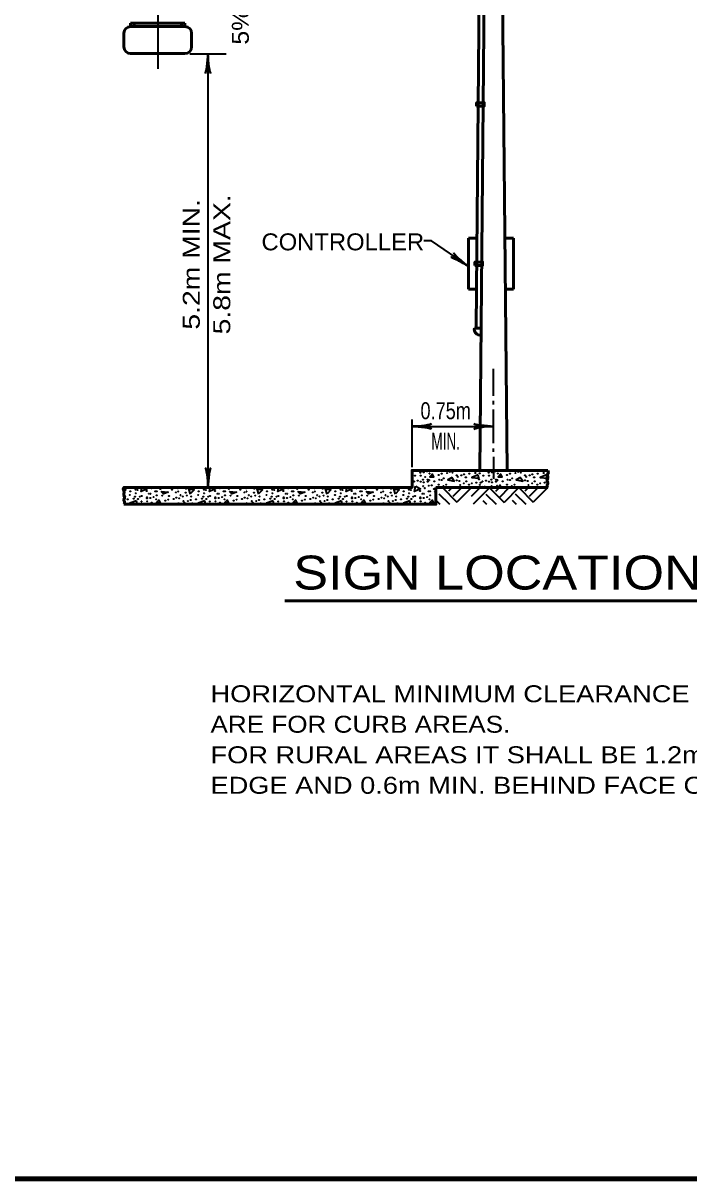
# Model space of a CAD drawing. Extents: x -35 to 821, y -10 to 534.
# Drawn here: x 357.6 to 475.5, y 1.2 to 205.9 of the extents above; entities that cross this region are included whole.
import ezdxf
from ezdxf.enums import TextEntityAlignment as Align

# ---------------------------------------------------------------- set-up
doc = ezdxf.new("R2010")
doc.units = 0
doc.header["$LTSCALE"] = 1.2
doc.layers.add('1', color=7, linetype='Continuous', lineweight=35)

msp = doc.modelspace()

# ---------------------------------------------------------------- linework, layer by layer
at = {"layer": '1', "lineweight": 53}
for p, q in [((439.528, 239.184), (438.487, 126.685)), ((442.245, 239.184), (443.287, 126.685)), ((438.395, 213.985), (437.884, 158.795)), ((376.67, 205.885), (386.27, 205.885)), ((376.67, 205.885), (376.67, 205.285)), ((376.67, 205.285), (386.27, 205.285)), ((377.27, 205.885), (377.27, 205.285)), ((385.67, 205.885), (385.67, 205.285)), ((386.27, 205.885), (386.27, 205.285)), ((375.47, 204.085), (375.47, 201.685)), ((387.47, 204.085), (387.47, 201.685)), ((376.67, 200.485), (386.27, 200.485)), ((436.467, 167.787), (436.467, 158.795)), ((437.967, 167.787), (436.467, 167.787)), ((444.405, 167.787), (442.906, 167.787)), ((444.405, 167.787), (444.405, 158.795)), ((437.884, 158.795), (436.467, 158.795)), ((437.884, 158.795), (437.82, 151.883)), ((444.405, 158.795), (442.989, 158.795)), ((438.72, 151.883), (437.52, 151.883)), ((450.487, 123.685), (430.687, 123.685)), ((403.971, 103.606), (518.449, 103.606))]:
    msp.add_line(p, q, dxfattribs=at)
at = {"layer": '1'}
for p, q in [((381.47, 211.285), (381.47, 197.779)), ((387.17, 200.438), (393.594, 200.438)), ((390.36, 200.438), (390.36, 123.685)), ((440.887, 139.885), (440.887, 144.685)), ((440.887, 138.385), (440.887, 138.985)), ((440.887, 131.485), (440.887, 137.485)), ((426.487, 127.285), (426.487, 135.685)), ((426.487, 134.485), (440.887, 134.485)), ((440.887, 129.985), (440.887, 130.585)), ((440.887, 129.085), (440.887, 125.185)), ((430.432, 122.984), (430.687, 122.955)), ((430.687, 122.729), (430.432, 122.984)), ((431.863, 123.637), (434.431, 121.069)), ((433.567, 123.637), (432.943, 123.013)), ((435.295, 123.637), (433.711, 122.053)), ((436.999, 123.637), (434.431, 121.069)), ((438.535, 123.637), (436.951, 122.053)), ((440.239, 123.637), (437.287, 120.685)), ((439.131, 123.685), (439.168, 123.944)), ((439.216, 123.92), (439.628, 123.685)), ((440.119, 123.637), (442.759, 120.997)), ((441.943, 123.637), (441.271, 122.941)), ((443.671, 123.637), (442.015, 121.981)), ((445.375, 123.637), (442.759, 120.997)), ((445.375, 123.637), (447.943, 121.069)), ((447.079, 123.637), (446.455, 123.013)), ((448.807, 123.637), (447.223, 122.053)), ((450.511, 123.637), (447.943, 121.069)), ((385.192, 120.872), (384.848, 120.685)), ((385.28, 120.685), (385.144, 120.896)), ((397.288, 120.872), (396.944, 120.685)), ((397.376, 120.685), (397.24, 120.896)), ((409.384, 120.872), (409.04, 120.685)), ((409.472, 120.685), (409.336, 120.896)), ((421.48, 120.872), (421.136, 120.685)), ((421.568, 120.685), (421.432, 120.896)), ((430.687, 121.405), (431.407, 120.685)), ((431.239, 122.557), (433.111, 120.685)), ((438.991, 121.333), (439.639, 120.685)), ((439.543, 122.485), (441.362, 120.685)), ((444.199, 121.405), (444.919, 120.685)), ((444.751, 122.557), (446.623, 120.685))]:
    msp.add_line(p, q, dxfattribs=at)
at = {"layer": '1', "lineweight": 158}
msp.add_line((814.384, 1.25), (22.784, 1.25), dxfattribs=at)
at = {"layer": '1', "lineweight": 53}
for points in [[(437.894, 191.186), (437.894, 191.786), (439.244, 191.786), (439.244, 191.186)], [(437.603, 162.988), (437.603, 163.588), (438.953, 163.588), (438.953, 162.988)]]:
    msp.add_lwpolyline(points, close=True, dxfattribs=at)
at = {"layer": '1'}
for points in [[(436.444, 162.857), (429.937, 167.319), (428.552, 167.319)], [(430.096, 126.056), (429.64, 125.576), (430.336, 125.528), (430.096, 126.008)], [(433.576, 125.432), (432.784, 125), (433.96, 124.784), (433.528, 125.456)], [(438.16, 125.888), (437.032, 125.432), (438.28, 125.288), (438.16, 125.84)], [(442.192, 126.056), (441.736, 125.576), (442.432, 125.528), (442.192, 126.008)], [(445.672, 125.432), (444.88, 125), (446.056, 124.784), (445.624, 125.456)], [(450.256, 125.888), (449.128, 125.432), (450.376, 125.288), (450.256, 125.84)], [(375.354, 123.341), (375.808, 123.248), (375.508, 122.927)], [(379.148, 123.685), (379.576, 123.44), (378.544, 122.936), (378.651, 123.685)], [(387.256, 122.48), (386.968, 123.44), (387.904, 123.248), (387.232, 122.528)], [(391.244, 123.685), (391.672, 123.44), (390.64, 122.936), (390.747, 123.685)], [(399.352, 122.48), (399.064, 123.44), (400, 123.248), (399.328, 122.528)], [(403.34, 123.685), (403.768, 123.44), (402.736, 122.936), (402.843, 123.685)], [(411.448, 122.48), (411.16, 123.44), (412.096, 123.248), (411.424, 122.528)], [(415.436, 123.685), (415.864, 123.44), (414.832, 122.936), (414.939, 123.685)], [(423.544, 122.48), (423.256, 123.44), (424.192, 123.248), (423.52, 122.528)], [(427.12, 123.92), (427.96, 123.44), (426.928, 122.936), (427.072, 123.944)], [(377.68, 121.328), (376.552, 120.872), (377.8, 120.728), (377.68, 121.28)], [(381.712, 121.496), (381.256, 121.016), (381.952, 120.968), (381.712, 121.448)], [(389.776, 121.328), (388.648, 120.872), (389.896, 120.728), (389.776, 121.28)], [(393.808, 121.496), (393.352, 121.016), (394.048, 120.968), (393.808, 121.448)], [(401.872, 121.328), (400.744, 120.872), (401.992, 120.728), (401.872, 121.28)], [(405.904, 121.496), (405.448, 121.016), (406.144, 120.968), (405.904, 121.448)], [(413.968, 121.328), (412.84, 120.872), (414.088, 120.728), (413.968, 121.28)], [(418, 121.496), (417.544, 121.016), (418.24, 120.968), (418, 121.448)], [(426.064, 121.328), (424.936, 120.872), (426.184, 120.728), (426.064, 121.28)], [(430.096, 121.496), (429.64, 121.016), (430.336, 120.968), (430.096, 121.448)]]:
    msp.add_lwpolyline(points, dxfattribs=at)
at = {"layer": '1', "lineweight": 53}
for points in [[(375.487, 120.685), (375.596, 120.843), (375.602, 121.098), (375.471, 121.392), (375.491, 121.562), (375.628, 121.89), (375.478, 122.302), (375.445, 122.492), (375.511, 122.897), (375.491, 123.087), (375.354, 123.342), (375.487, 123.685), (426.487, 123.685), (426.487, 126.685), (450.487, 126.685)], [(450.487, 126.685), (450.62, 126.342), (450.482, 126.087), (450.463, 125.897), (450.528, 125.492), (450.495, 125.302), (450.345, 124.89), (450.482, 124.562), (450.502, 124.392), (450.371, 124.098), (450.377, 123.843), (450.487, 123.685)], [(430.687, 123.685), (430.687, 120.685), (375.487, 120.685)]]:
    msp.add_lwpolyline(points, dxfattribs=at)
at = {"layer": '1'}
for points in [[(382.048, 122.984), (383.296, 122.84), (382.48, 122.552)], [(394.144, 122.984), (395.392, 122.84), (394.576, 122.552)], [(406.24, 122.984), (407.488, 122.84), (406.672, 122.552)], [(418.336, 122.984), (419.584, 122.84), (418.768, 122.552)]]:
    msp.add_lwpolyline(points, close=True, dxfattribs=at)
for centre in [(426.679, 126.58), (426.981, 125.743), (427.474, 124.868), (427.935, 126.3), (427.951, 126.501), (427.983, 125.759), (428.396, 125.043), (428.539, 126.363), (428.794, 125.536), (429.128, 126.517), (429.223, 125.059), (429.503, 124.963), (429.566, 126.141), (431.173, 125.886), (431.3, 125.027), (431.713, 126.093), (431.713, 124.979), (432.095, 125.266), (432.684, 126.204), (433.161, 126.437), (433.638, 126.284), (434.306, 126.628), (434.385, 125.807), (434.385, 124.916), (434.576, 125.552), (434.846, 124.804), (435.196, 125.807), (435.673, 125.998), (435.785, 126.628), (435.944, 125.441), (436.007, 125.441), (436.612, 126.125), (437.677, 126.236), (437.932, 126.612), (438.313, 125.122), (438.441, 126.188), (438.775, 126.58), (439.077, 125.743), (439.57, 124.868), (440.031, 126.3), (440.047, 126.501), (440.079, 125.759), (440.492, 125.043), (440.635, 126.363), (440.89, 125.536), (441.224, 126.517), (441.319, 125.059), (441.599, 124.963), (441.662, 126.141), (443.269, 125.886), (443.396, 125.027), (443.809, 126.093), (443.809, 124.979), (444.191, 125.266), (444.78, 126.204), (445.257, 126.437), (445.734, 126.284), (446.402, 126.628), (446.481, 125.807), (446.481, 124.916), (446.672, 125.552), (446.942, 124.804), (447.292, 125.807), (447.769, 125.998), (447.881, 126.628), (448.04, 125.441), (448.103, 125.441), (448.708, 126.125), (449.773, 126.236), (450.028, 126.612), (376.609, 122.975), (377.547, 123.277), (377.897, 123.198), (379.519, 123.023), (380.346, 123.547), (381.022, 122.988), (381.294, 123.007), (381.946, 123.404), (383.981, 123.277), (384.697, 122.784), (385.031, 123.547), (385.079, 122.959), (386.399, 122.752), (386.447, 123.468), (388.705, 122.975), (389.643, 123.277), (389.993, 123.198), (391.615, 123.023), (392.442, 123.547), (393.118, 122.988), (393.39, 123.007), (394.042, 123.404), (396.077, 123.277), (396.793, 122.784), (397.127, 123.547), (397.175, 122.959), (398.495, 122.752), (398.543, 123.468), (400.801, 122.975), (401.739, 123.277), (402.089, 123.198), (403.711, 123.023), (404.538, 123.547), (405.214, 122.988), (405.486, 123.007), (406.138, 123.404), (408.173, 123.277), (408.889, 122.784), (409.223, 123.547), (409.271, 122.959), (410.591, 122.752), (410.639, 123.468), (412.897, 122.975), (413.835, 123.277), (414.185, 123.198), (415.807, 123.023), (416.634, 123.547), (417.31, 122.988), (417.582, 123.007), (418.234, 123.404), (420.269, 123.277), (420.985, 122.784), (421.319, 123.547), (421.367, 122.959), (422.687, 122.752), (422.735, 123.468), (424.993, 122.975), (425.931, 123.277), (426.281, 123.198), (426.838, 124.725), (427.903, 123.023), (428.015, 124.693), (428.46, 123.898), (428.524, 124.566), (428.73, 123.547), (429.239, 124.677), (429.406, 122.988), (429.43, 123.961), (429.678, 123.007), (429.932, 124.025), (430.33, 123.404), (430.441, 124.757), (431.204, 124.152), (432.031, 123.898), (432.509, 124.152), (433.908, 123.754), (434.99, 124.12), (435.642, 124.407), (436.087, 124.741), (436.564, 124.152), (437.057, 124.423), (437.836, 124.534), (438.393, 123.77), (438.473, 124.136), (438.6, 124.518), (438.934, 124.725), (440.111, 124.693), (440.556, 123.898), (440.62, 124.566), (441.335, 124.677), (441.526, 123.961), (442.028, 124.025), (442.537, 124.757), (443.3, 124.152), (444.127, 123.898), (444.605, 124.152), (446.004, 123.754), (447.086, 124.12), (447.738, 124.407), (448.183, 124.741), (448.66, 124.152), (449.153, 124.423), (449.932, 124.534), (376.132, 121.565), (376.529, 122.323), (377.197, 121.676), (377.452, 122.052), (377.563, 122.657), (377.961, 121.628), (378.295, 122.02), (378.597, 121.183), (378.629, 122.163), (379.551, 121.74), (379.567, 121.941), (379.599, 121.199), (379.917, 122.545), (380.155, 121.803), (380.187, 122.545), (380.41, 120.976), (380.744, 121.957), (381.182, 121.581), (381.294, 122.291), (382.264, 122.243), (382.789, 121.326), (383.329, 121.533), (383.457, 122.148), (384.3, 121.644), (384.777, 121.877), (385.254, 121.724), (385.492, 122.307), (385.922, 122.068), (386.001, 121.247), (386.192, 120.992), (386.621, 122.243), (386.812, 121.247), (387.289, 121.438), (387.401, 122.068), (387.56, 120.881), (387.623, 120.881), (388.228, 121.565), (388.625, 122.323), (389.293, 121.676), (389.548, 122.052), (389.659, 122.657), (390.057, 121.628), (390.391, 122.02), (390.693, 121.183), (390.725, 122.163), (391.647, 121.74), (391.663, 121.941), (391.695, 121.199), (392.013, 122.545), (392.251, 121.803), (392.283, 122.545), (392.506, 120.976), (392.84, 121.957), (393.278, 121.581), (393.39, 122.291), (394.36, 122.243), (394.885, 121.326), (395.425, 121.533), (395.553, 122.148), (396.396, 121.644), (396.873, 121.877), (397.35, 121.724), (397.588, 122.307), (398.018, 122.068), (398.097, 121.247), (398.288, 120.992), (398.717, 122.243), (398.908, 121.247), (399.385, 121.438), (399.497, 122.068), (399.656, 120.881), (399.719, 120.881), (400.324, 121.565), (400.721, 122.323), (401.389, 121.676), (401.644, 122.052), (401.755, 122.657), (402.153, 121.628), (402.487, 122.02), (402.789, 121.183), (402.821, 122.163), (403.743, 121.74), (403.759, 121.941), (403.791, 121.199), (404.109, 122.545), (404.347, 121.803), (404.379, 122.545), (404.602, 120.976), (404.936, 121.957), (405.374, 121.581), (405.486, 122.291), (406.456, 122.243), (406.981, 121.326), (407.521, 121.533), (407.649, 122.148), (408.492, 121.644), (408.969, 121.877), (409.446, 121.724), (409.684, 122.307), (410.114, 122.068), (410.193, 121.247), (410.384, 120.992), (410.813, 122.243), (411.004, 121.247), (411.481, 121.438), (411.593, 122.068), (411.752, 120.881), (411.815, 120.881), (412.42, 121.565), (412.817, 122.323), (413.485, 121.676), (413.74, 122.052), (413.851, 122.657), (414.249, 121.628), (414.583, 122.02), (414.885, 121.183), (414.917, 122.163), (415.839, 121.74), (415.855, 121.941), (415.887, 121.199), (416.205, 122.545), (416.443, 121.803), (416.475, 122.545), (416.698, 120.976), (417.032, 121.957), (417.47, 121.581), (417.582, 122.291), (418.552, 122.243), (419.077, 121.326), (419.617, 121.533), (419.745, 122.148), (420.588, 121.644), (421.065, 121.877), (421.542, 121.724), (421.78, 122.307), (422.21, 122.068), (422.289, 121.247), (422.48, 120.992), (422.909, 122.243), (423.1, 121.247), (423.577, 121.438), (423.689, 122.068), (423.848, 120.881), (423.911, 120.881), (424.516, 121.565), (424.913, 122.323), (425.581, 121.676), (425.836, 122.052), (425.947, 122.657), (426.345, 121.628), (426.679, 122.02), (426.981, 121.183), (427.013, 122.163), (427.935, 121.74), (427.951, 121.941), (427.983, 121.199), (428.301, 122.545), (428.539, 121.803), (428.571, 122.545), (428.794, 120.976), (429.128, 121.957), (429.566, 121.581), (429.678, 122.291), (430.648, 122.243)]:
    msp.add_circle(centre, 0.0318, dxfattribs=at)
at = {"layer": '1', "lineweight": 53}
for centre, radius, start, end in [((376.67, 204.085), 1.2, 90, 180), ((386.27, 204.085), 1.2, 0, 90), ((376.67, 201.685), 1.2, 180, 270), ((386.27, 201.685), 1.2, 270, 0), ((438.475, 151.641), 0.986, 165.76102, 283.71131)]:
    msp.add_arc(centre, radius, start, end, dxfattribs=at)
at = {"layer": '1'}
for centre, start, end in [((431.841, 126.708), 226.35082, 313.64918), ((443.937, 126.708), 226.35082, 313.64918), ((450.409, 125.122), 32.83014, 287.06312), ((450.537, 126.188), 61.61934, 241.7845), ((376.418, 123.707), 223.9797, 316.0203), ((377.038, 123.675), 162.01481, 17.98519), ((382.757, 123.675), 162.01481, 17.98519), ((388.514, 123.707), 223.9797, 316.0203), ((389.134, 123.675), 162.01481, 17.98519), ((394.853, 123.675), 162.01481, 17.98519), ((400.61, 123.707), 223.9797, 316.0203), ((401.23, 123.675), 162.01481, 17.98519), ((406.949, 123.675), 162.01481, 17.98519), ((412.706, 123.707), 223.9797, 316.0203), ((413.326, 123.675), 162.01481, 17.98519), ((419.045, 123.675), 162.01481, 17.98519), ((424.802, 123.707), 223.9797, 316.0203), ((425.422, 123.675), 162.01481, 17.98519), ((426.504, 124.518), 237.37076, 122.62924), ((431.141, 123.675), 17.98519, 162.01481), ((436.898, 123.707), 316.0203, 223.9797), ((437.518, 123.675), 17.98519, 162.01481), ((443.237, 123.675), 17.98519, 162.01481), ((448.994, 123.707), 316.0203, 223.9797), ((449.614, 123.675), 17.98519, 162.01481), ((383.711, 120.706), 318.30023, 221.69977), ((395.807, 120.706), 318.30023, 221.69977), ((407.903, 120.706), 318.30023, 221.69977), ((419.999, 120.706), 318.30023, 221.69977)]:
    msp.add_arc(centre, 0.0318, start, end, dxfattribs=at)
at = {"layer": '1', "lineweight": 40}
for centre, major_axis, ratio, start_param, end_param in [((390.096, 199.083), (0.211, 2.108), 0.07063, 3.1407148, 5.41811), ((390.682, 199.118), (-0.187, 2.143), 0.122415, 0.8963533, 3.1415927), ((435.177, 163.406), (-1.858, 1.018), 0.07063, 4.006668, 6.2840632), ((435.537, 163.869), (1.661, -1.366), 0.122415, 3.1415927, 5.386832), ((427.831, 134.231), (-2.108, 0.211), 0.07063, 3.1407148, 5.41811), ((427.831, 134.231), (-2.108, 0.211), 0.07063, 3.1407148, 5.41811), ((427.796, 134.816), (-2.143, -0.187), 0.122415, 0.8963533, 3.1415927), ((427.796, 134.816), (-2.143, -0.187), 0.122415, 0.8963533, 3.1415927), ((439.577, 134.153), (2.143, 0.187), 0.122415, 0.8963533, 3.1415927), ((439.542, 134.739), (2.108, -0.211), 0.07063, 3.1407148, 5.41811), ((390.038, 125.005), (0.187, -2.143), 0.122415, 0.8963533, 3.1415927), ((390.624, 125.04), (-0.211, -2.108), 0.07063, 3.1407148, 5.41811)]:
    msp.add_ellipse(centre, major_axis=major_axis, ratio=ratio, start_param=start_param, end_param=end_param, dxfattribs=at)

# ---------------------------------------------------------------- texts
at = {"layer": '1'}
for s, width, p in [('5% MAX. SAG', 1.1, (397.584, 216.54)), ('5.2m MIN.', 1.25, (388.902, 163.174)), ('5.8m MAX.', 1.25, (394.302, 163.174))]:
    msp.add_text(s, height=3, rotation=90, dxfattribs=dict(at, width=width)).set_placement(p, align=Align.CENTER)
for s, height, width, p in [('CONTROLLER', 3, 1.05, (399.828, 165.657)), ('SIGN LOCATION DETAILS', 6, 1.15, (405.456, 105.603)), ('HORIZONTAL MINIMUM CLEARANCE (0.6m AND 0.75m) AS SHOWN', 3, 1.2, (390.808, 85.642)), ('ARE FOR CURB AREAS.', 3, 1.15, (390.808, 80.242)), ('FOR RURAL AREAS IT SHALL BE 1.2m MIN. BEHIND SHOULDER', 3, 1.2, (390.808, 74.842)), ('EDGE AND 0.6m MIN. BEHIND FACE OF GUARDRAIL.', 3, 1.2, (390.808, 69.442))]:
    msp.add_text(s, height=height, dxfattribs=dict(at, width=width)).set_placement(p)
for s, width, p in [('0.75m', 0.8, (432.429, 135.759)), ('MIN.', 0.6, (432.429, 130.359))]:
    msp.add_text(s, height=3, dxfattribs=dict(at, width=width)).set_placement(p, align=Align.CENTER)

doc.saveas('drawing.dxf')
